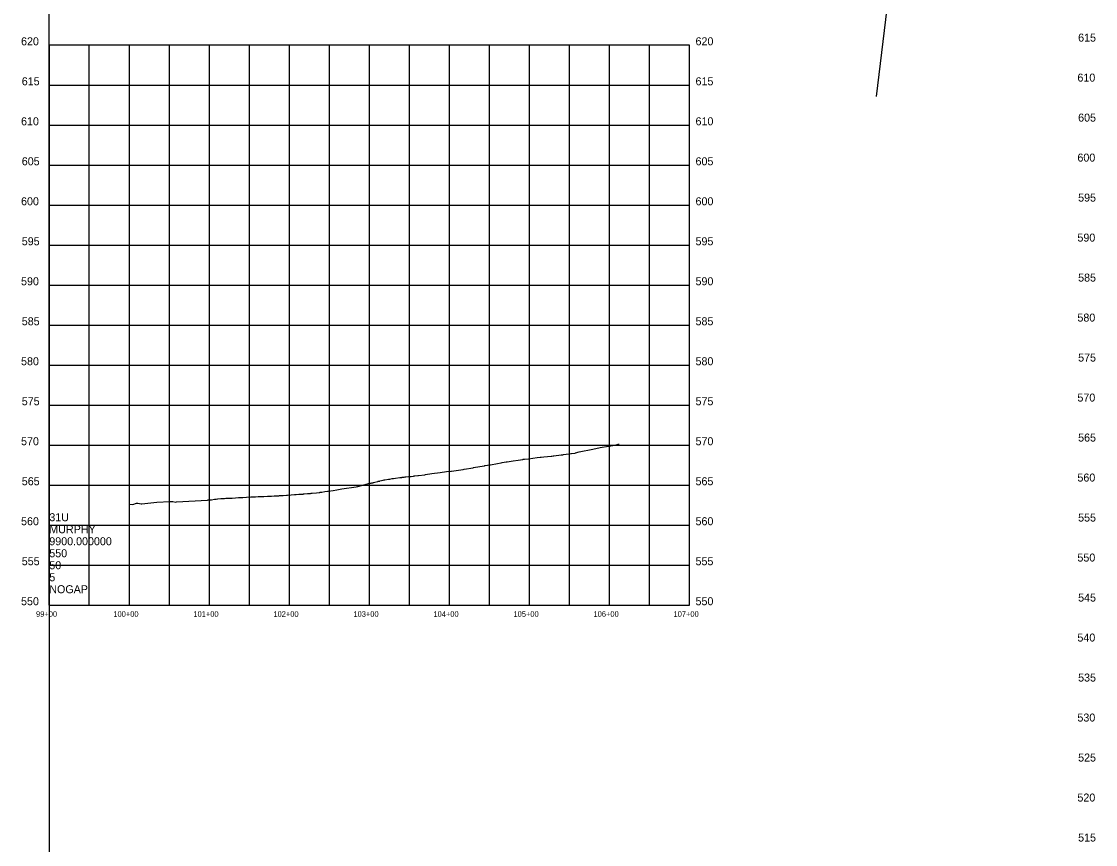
# Model space of a CAD drawing. Extents: x 1724534 to 1727318, y 654728 to 660023.
# Drawn here: x 1724534 to 1725876, y 657224 to 658253 of the extents above; entities that cross this region are included whole.
import ezdxf

# ---------------------------------------------------------------- set-up
doc = ezdxf.new("R2010")
doc.units = 0
for name, color, linetype in [('DESIGN - CENTERLINE - Proposed Text', 7, 'Continuous'), ('DESIGN - SHEET - Corner Text', 7, 'Continuous'), ('DESIGN - SHEET - Light Grid', 7, 'Continuous'), ('SURVEY - PROFILE - Ground Line with Text', 7, 'Continuous')]:
    doc.layers.add(name, color=color, linetype=linetype)

msp = doc.modelspace()

# ---------------------------------------------------------------- linework, layer by layer
at = {"layer": 'DESIGN - CENTERLINE - Proposed Text'}
msp.add_line((1725602.2, 658159), (1725642.8, 658493.6), dxfattribs=at)
at = {"layer": 'DESIGN - SHEET - Light Grid'}
for p, q in [((1724568.6, 657523), (1724568.6, 660023)), ((1725368.6, 658223), (1724568.6, 658223)), ((1724568.6, 658223), (1724568.6, 657523)), ((1724618.6, 657523), (1724618.6, 658223)), ((1724668.6, 657523), (1724668.6, 658223)), ((1724718.6, 657523), (1724718.6, 658223)), ((1724768.6, 657523), (1724768.6, 658223)), ((1724818.6, 657523), (1724818.6, 658223)), ((1724868.6, 657523), (1724868.6, 658223)), ((1724918.6, 657523), (1724918.6, 658223)), ((1724968.6, 657523), (1724968.6, 658223)), ((1725018.6, 657523), (1725018.6, 658223)), ((1725068.6, 657523), (1725068.6, 658223)), ((1725118.6, 657523), (1725118.6, 658223)), ((1725168.6, 657523), (1725168.6, 658223)), ((1725218.6, 657523), (1725218.6, 658223)), ((1725268.6, 657523), (1725268.6, 658223)), ((1725318.6, 657523), (1725318.6, 658223)), ((1725368.6, 657523), (1725368.6, 658223)), ((1724568.6, 658173), (1725368.6, 658173)), ((1724568.6, 658123), (1725368.6, 658123)), ((1724568.6, 658073), (1725368.6, 658073)), ((1724568.6, 658023), (1725368.6, 658023)), ((1724568.6, 657973), (1725368.6, 657973)), ((1724568.6, 657923), (1725368.6, 657923)), ((1724568.6, 657873), (1725368.6, 657873)), ((1724568.6, 657823), (1725368.6, 657823)), ((1724568.6, 657773), (1725368.6, 657773)), ((1724568.6, 657723), (1725368.6, 657723)), ((1724568.6, 657673), (1725368.6, 657673)), ((1724568.6, 657623), (1725368.6, 657623)), ((1724568.6, 657573), (1725368.6, 657573)), ((1724568.6, 657523), (1725268.6, 657523)), ((1724568.6, 657523), (1724568.6, 655023)), ((1724568.6, 657523), (1725368.6, 657523))]:
    msp.add_line(p, q, dxfattribs=at)
at = {"layer": 'SURVEY - PROFILE - Ground Line with Text'}
for points in [[(1725226, 657713.4), (1725230.5, 657714.6), (1725247.6, 657718.2), (1725256.8, 657720.3), (1725267.5, 657721.8), (1725275.7, 657723.3), (1725279.4, 657724.2), (1725280.8, 657724.5)], [(1724927.8, 657667.3), (1724934.1, 657668.4), (1724952, 657671.2), (1724954, 657671.6), (1724969.2, 657675.5), (1724969.6, 657675.6), (1724970.6, 657675.7), (1724971.6, 657675.9), (1724973.2, 657676.2), (1724973.9, 657676.3), (1724975.5, 657676.8), (1724979.1, 657677.8), (1724979.6, 657677.9), (1724981.5, 657678.3), (1724981.8, 657678.4), (1724985.6, 657679.2), (1724985.7, 657679.3), (1724987.1, 657679.6), (1724987.8, 657679.7), (1724992.3, 657680.5), (1724994.1, 657680.7), (1724997.1, 657681.3), (1724997.2, 657681.3), (1724998.6, 657681.5), (1725001.1, 657681.9), (1725006.6, 657682.6), (1725008.1, 657682.7), (1725009, 657682.8), (1725009.4, 657682.9), (1725011.9, 657683.2), (1725013.1, 657683.4), (1725013.6, 657683.4), (1725013.9, 657683.4), (1725017.4, 657683.8), (1725020.9, 657684.1), (1725023.2, 657684.4), (1725023.6, 657684.5), (1725024.4, 657684.6), (1725025.3, 657684.7), (1725029, 657685.1), (1725029.5, 657685.1), (1725029.8, 657685.2), (1725037.7, 657686.1), (1725038.7, 657686.3), (1725046.5, 657687.5), (1725046.6, 657687.5), (1725046.8, 657687.5), (1725056.9, 657689.1), (1725064.8, 657690), (1725070.4, 657690.6), (1725071.1, 657690.7), (1725071.3, 657690.7), (1725076.9, 657691.5), (1725077.1, 657691.6), (1725085.9, 657692.8), (1725086.8, 657693), (1725087.2, 657693), (1725098.2, 657694.9), (1725098.7, 657695), (1725106.5, 657696.4), (1725112.4, 657697.4), (1725112.9, 657697.6), (1725113.2, 657697.6), (1725119, 657698.5), (1725119.1, 657698.5), (1725120.1, 657698.6), (1725128.6, 657700.1), (1725133.2, 657701), (1725134.4, 657701.3), (1725134.4, 657701.3), (1725139.3, 657702.2), (1725139.6, 657702.2), (1725140.6, 657702.4), (1725148.2, 657703.6), (1725154.4, 657704.5), (1725154.5, 657704.5), (1725160.5, 657705.3), (1725160.9, 657705.4), (1725162.3, 657705.5), (1725167.2, 657706.2), (1725178.2, 657707.7), (1725182.1, 657708), (1725182.5, 657708.1), (1725183.1, 657708.1), (1725186.4, 657708.4), (1725186.7, 657708.5), (1725195.9, 657709.4), (1725196.4, 657709.5), (1725198.1, 657709.7), (1725198.7, 657709.8), (1725199.2, 657709.8), (1725208, 657710.9), (1725208.7, 657711), (1725210.4, 657711.2), (1725211.2, 657711.3), (1725217.9, 657712.2), (1725218.8, 657712.4), (1725220.4, 657712.5), (1725221.3, 657712.7), (1725225.8, 657713.3), (1725226, 657713.4)], [(1724668.6, 657649.2), (1724672.8, 657649.1), (1724677.4, 657650.5), (1724679.3, 657650.6), (1724683.5, 657649.7), (1724684.3, 657649.7), (1724702.8, 657651.8), (1724719.2, 657652.6), (1724722.9, 657652.8), (1724726.7, 657652), (1724727.6, 657652.1), (1724766.3, 657654.5), (1724767.2, 657654.6), (1724768.1, 657654.6), (1724769, 657654.7), (1724770.7, 657654.8), (1724771.4, 657654.9), (1724774.9, 657655.5), (1724775.3, 657655.6), (1724777.1, 657655.8), (1724778.9, 657656.2), (1724779.1, 657656.2), (1724783, 657656.4), (1724783.3, 657656.4), (1724784.8, 657656.5), (1724785, 657656.5), (1724786.3, 657656.6), (1724787.6, 657656.6), (1724789, 657656.7), (1724790.2, 657656.7), (1724791.3, 657656.7), (1724793.7, 657656.8), (1724794.9, 657656.9), (1724794.9, 657656.9), (1724795, 657656.9), (1724796.1, 657657), (1724797.3, 657657), (1724801.4, 657657.3), (1724804.8, 657657.5), (1724804.8, 657657.5), (1724805, 657657.5), (1724810.6, 657657.8), (1724814.9, 657658.1), (1724814.9, 657658.1), (1724815, 657658.1), (1724820.6, 657658.5), (1724825, 657658.7), (1724825.3, 657658.7), (1724826.1, 657658.7), (1724826.2, 657658.7), (1724829.6, 657658.8), (1724834.1, 657658.9), (1724834.5, 657658.9), (1724835.9, 657659), (1724836.6, 657659), (1724841.1, 657659.2), (1724845, 657659.4), (1724845.8, 657659.4), (1724845.9, 657659.4), (1724846.3, 657659.4), (1724849.6, 657659.6), (1724854.1, 657659.9), (1724855.2, 657659.9), (1724855.6, 657659.9), (1724856.3, 657660), (1724860.7, 657660.3), (1724865, 657660.5), (1724865.6, 657660.5), (1724865.8, 657660.5), (1724866.3, 657660.6), (1724870.7, 657661), (1724875, 657661.4), (1724875.7, 657661.4), (1724876, 657661.4), (1724876.5, 657661.4), (1724877, 657661.4), (1724880.3, 657661.8), (1724883.9, 657662), (1724885.8, 657662), (1724885.9, 657662), (1724886.2, 657662.1), (1724887, 657662.1), (1724891.4, 657662.5), (1724895, 657662.8), (1724896, 657662.9), (1724896.3, 657662.9), (1724896.4, 657662.9), (1724897, 657663), (1724902.5, 657663.6), (1724906.1, 657664.1), (1724906.5, 657664.1), (1724906.7, 657664.2), (1724907.3, 657664.2), (1724909.2, 657664.5), (1724912.8, 657665), (1724916.1, 657665.4), (1724916.9, 657665.6), (1724917, 657665.6), (1724917.1, 657665.6), (1724923.2, 657666.5), (1724927.8, 657667.3)]]:
    msp.add_lwpolyline(points, dxfattribs=at)

# ---------------------------------------------------------------- texts
at = {"layer": 'DESIGN - SHEET - Corner Text'}
for s, height, p in [('620', 10, (1724533.3, 658223)), ('620', 10, (1725376.1, 658223)), ('615', 10, (1725854.2, 658227.6)), ('615', 10, (1724534.2, 658173)), ('615', 10, (1725376.1, 658173)), ('610', 10, (1725853.3, 658177.6)), ('605', 10, (1725854.2, 658127.6)), ('610', 10, (1724533.3, 658123)), ('610', 10, (1725376.1, 658123)), ('605', 10, (1724534.2, 658073)), ('605', 10, (1725376.1, 658073)), ('600', 10, (1725853.3, 658077.6)), ('600', 10, (1724533.3, 658023)), ('600', 10, (1725376.1, 658023)), ('595', 10, (1725854.2, 658027.6)), ('590', 10, (1725853.3, 657977.6)), ('595', 10, (1724534.2, 657973)), ('595', 10, (1725376.1, 657973)), ('585', 10, (1725854.2, 657927.6)), ('590', 10, (1724533.3, 657923)), ('590', 10, (1725376.1, 657923)), ('585', 10, (1724534.2, 657873)), ('585', 10, (1725376.1, 657873)), ('580', 10, (1725853.3, 657877.6)), ('580', 10, (1724533.3, 657823)), ('580', 10, (1725376.1, 657823)), ('575', 10, (1725854.2, 657827.6)), ('570', 10, (1725853.3, 657777.6)), ('575', 10, (1724534.2, 657773)), ('575', 10, (1725376.1, 657773)), ('570', 10, (1724533.3, 657723)), ('570', 10, (1725376.1, 657723)), ('565', 10, (1725854.2, 657727.6)), ('565', 10, (1724534.2, 657673)), ('565', 10, (1725376.1, 657673)), ('560', 10, (1725853.3, 657677.6)), ('560', 10, (1724533.3, 657623)), ('560', 10, (1725376.1, 657623)), ('555', 10, (1725854.2, 657627.6)), ('550', 10, (1725853.3, 657577.6)), ('555', 10, (1724534.2, 657573)), ('555', 10, (1725376.1, 657573)), ('550', 10, (1724533.3, 657523)), ('550', 10, (1725376.1, 657523)), ('545', 10, (1725854.2, 657527.6)), ('99+00', 7, (1724552, 657508.5)), ('100+00', 7, (1724648.6, 657508.5)), ('101+00', 7, (1724748.6, 657508.5)), ('102+00', 7, (1724848.6, 657508.5)), ('103+00', 7, (1724948.6, 657508.5)), ('104+00', 7, (1725048.6, 657508.5)), ('105+00', 7, (1725148.6, 657508.5)), ('106+00', 7, (1725248.6, 657508.5)), ('107+00', 7, (1725348.6, 657508.5)), ('540', 10, (1725853.3, 657477.6)), ('535', 10, (1725854.2, 657427.6)), ('530', 10, (1725853.3, 657377.6)), ('525', 10, (1725854.2, 657327.6)), ('520', 10, (1725853.3, 657277.6)), ('515', 10, (1725854.2, 657227.6))]:
    msp.add_text(s, height=height, dxfattribs=at).set_placement(p)
at = {"layer": 'DESIGN - SHEET - Light Grid'}
for s, p in [('31U', (1724568.6, 657628)), ('MURPHY', (1724568.6, 657613)), ('9900.000000', (1724568.6, 657598)), ('550', (1724568.6, 657583)), ('50', (1724568.6, 657568)), ('5', (1724568.6, 657553)), ('NOGAP', (1724568.6, 657538))]:
    msp.add_text(s, height=10, dxfattribs=at).set_placement(p)

doc.saveas('drawing.dxf')
